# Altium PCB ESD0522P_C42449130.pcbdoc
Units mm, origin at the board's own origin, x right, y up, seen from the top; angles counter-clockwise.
Board outline 14.65 x 14.22 mm, 2 copper layers (Top Layer, Bottom Layer), stack 0 mm thick; 1 components, 0 nets, 6 pads, 0 vias.
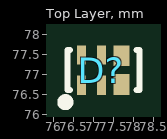
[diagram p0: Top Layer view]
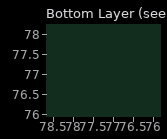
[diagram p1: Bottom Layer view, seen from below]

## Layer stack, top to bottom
Top Layer: signal copper (thickness not stored)
Bottom Layer: signal copper (thickness not stored)

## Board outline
84.5,69.85 69.85,69.85 69.85,84.068 84.5,84.068

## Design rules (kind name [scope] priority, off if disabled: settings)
PasteMaskExpansion "Paste Mask Expansion" [All] p1: expansion=0
SolderMaskExpansion "Solder Mask Expansion" [IsVia] p1: expansion=-25.4 istentingtop=TRUE
SolderMaskExpansion "Solder Mask Expansion" [All] p2: expansion=0.051 istentingtop=FALSE

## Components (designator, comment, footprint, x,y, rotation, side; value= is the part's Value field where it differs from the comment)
D? "ESD0522P" UDFN-6_L1.6-W1.0-P0.50-BL 77.2,77.1 r0 top

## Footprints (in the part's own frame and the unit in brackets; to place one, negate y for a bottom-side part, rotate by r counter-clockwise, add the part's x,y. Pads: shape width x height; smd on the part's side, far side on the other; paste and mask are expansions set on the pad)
UDFN-6_L1.6-W1.0-P0.50-BL [mm]
  rect 0.22x0.48 smd: 1(-0.5,-0.378) 2(0,-0.378) 5(0,0.378) 6(-0.5,0.377)
  rect 0.4x0.521 smd: 3(0.5,-0.358)
  rect 0.4x0.51 smd: 4(0.5,0.362)
  silkscreen extent -1,-0.9 0.95,0.5

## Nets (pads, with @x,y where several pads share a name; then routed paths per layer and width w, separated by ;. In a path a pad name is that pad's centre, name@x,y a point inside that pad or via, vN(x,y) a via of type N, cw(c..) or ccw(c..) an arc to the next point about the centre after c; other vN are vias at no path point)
pads on no net: D?.1 D?.2 D?.3 D?.4 D?.5 D?.6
